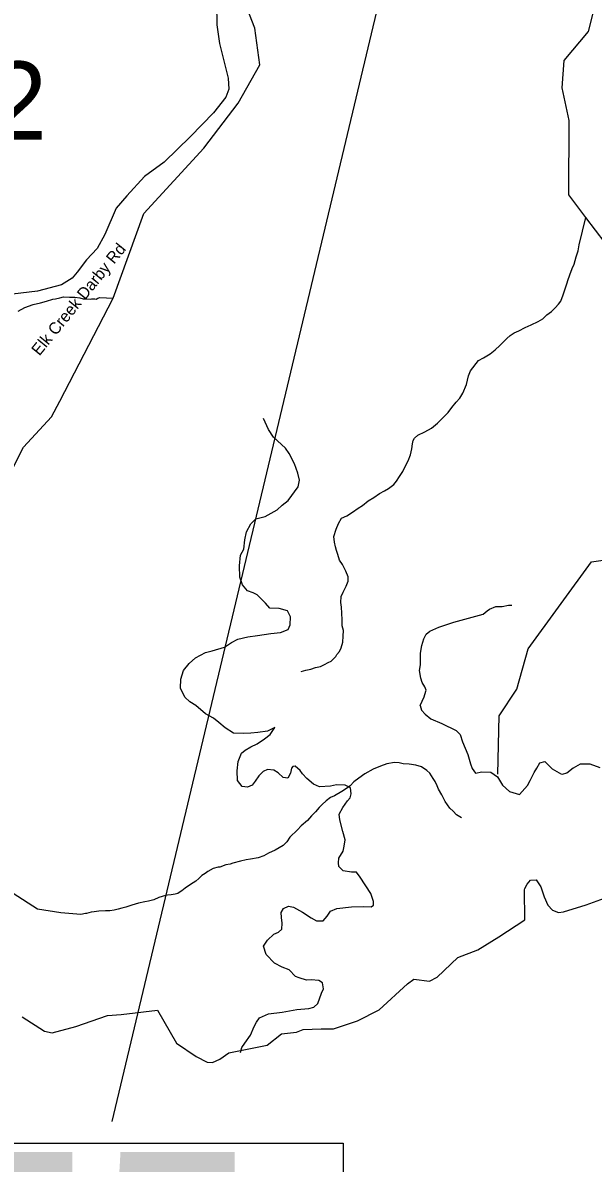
# Model space of a CAD drawing. Extents: x 1248224 to 1454986, y 825081 to 985870.
# Drawn here: x 1257767 to 1261423, y 862920 to 870230 of the extents above; entities that cross this region are included whole.
import ezdxf

# ---------------------------------------------------------------- set-up
doc = ezdxf.new("R2010")
doc.units = 0
for name, color, linetype in [('Exist Boundary Political CountyLine', 7, 'Continuous'), ('Exist Hydrographic Creek Single Shore', 7, 'Continuous'), ('Exist Hydrographic Misc Water Feature', 7, 'Continuous'), ('Exist Road Non-System Type 51', 7, 'Continuous'), ('Exist Road Secondary Structure Standard Bridge Number Label', 7, 'Continuous'), ('Exist Road Secondary Type 51 Attributed', 7, 'Continuous'), ('Exist Road Secondary Type 51 Label', 7, 'Continuous'), ('Exist Road Secondary Type 51 Number Label', 7, 'Continuous')]:
    doc.layers.add(name, color=color, linetype=linetype)

msp = doc.modelspace()

# ---------------------------------------------------------------- linework, layer by layer
at = {"layer": 'Exist Boundary Political CountyLine'}
for points in [[(1260985.6, 864480), (1260982.6, 864672), (1260983.6, 864680.2), (1260999.6, 864708.4), (1261021.6, 864734.8), (1261057.6, 864736.6), (1261087.6, 864691.6), (1261108.6, 864626.1), (1261131.6, 864572.8), (1261162.6, 864540.6), (1261199.6, 864527.6), (1261232.6, 864529.9), (1261377.6, 864575.3), (1261517.6, 864627.3)], [(1257763.5, 863857.1), (1257906.6, 863764.9), (1257954.3, 863755.3), (1258106.9, 863796.7), (1258308.9, 863866.7), (1258397.9, 863873), (1258629.6, 863900.8), (1258752.4, 863688.5), (1258878, 863602.6), (1258948, 863567.6), (1258983, 863564.4), (1259030.7, 863586.7), (1259087.9, 863628), (1259332.6, 863675.6), (1259424.9, 863748.9), (1259520.3, 863758.5), (1259564.8, 863777.6), (1259679.3, 863780.8), (1259758.8, 863780.8), (1259911.4, 863831.7), (1260051.3, 863901.7), (1260232.6, 864070.3), (1260272.3, 864098.9), (1260374.1, 864086.2), (1260421.8, 864111.7), (1260555.3, 864238.9), (1260682.5, 864286.7), (1260818.6, 864369.9), (1260985.6, 864480)]]:
    msp.add_lwpolyline(points, dxfattribs=at)
at = {"layer": 'Exist Hydrographic Creek Single Shore'}
for points in [[(1261646.5, 868709.1), (1261498.5, 868820.4), (1261375.5, 868982.3), (1261265.5, 869127.1), (1261269.5, 869603), (1261224.5, 869814), (1261237.4, 869987.8), (1261392.4, 870175), (1261475.5, 870508.2)], [(1258139.6, 864512.9), (1258010.5, 864524.3), (1257861.6, 864547), (1257705.6, 864648.6), (1257624.5, 864745.4), (1257452.6, 865198.6), (1257447.6, 865300.4), (1257198.5, 865705.9), (1257237.5, 865912), (1257176.5, 866113.4), (1257193.5, 866474.1), (1257403.5, 866850.7), (1257433.5, 867017.6), (1257691.5, 867353.8), (1257771.5, 867509.9), (1257951.5, 867703.1), (1258003.5, 867803.9), (1258346.9, 868463.9), (1258543.5, 869007.7), (1258926.5, 869427.1), (1259146.4, 869715.2), (1259287.1, 869960.8), (1259254.6, 870194.7), (1259150.8, 870460.3)], [(1257737.1, 868382), (1257779.7, 868405), (1257834.2, 868423.6), (1257880.5, 868434.4), (1257918.9, 868445.4), (1257959.3, 868458.4), (1257977.2, 868459.9), (1258003.5, 868467.2), (1258027.6, 868472.6), (1258065.6, 868471.6), (1258099.6, 868470.7), (1258131.5, 868465.9), (1258153.3, 868461.3), (1258177.3, 868460.7), (1258199.4, 868458.1), (1258207.4, 868460), (1258229.3, 868459.4), (1258237.3, 868459.2), (1258247.6, 868465), (1258261.6, 868468.6), (1258346.9, 868463.9)]]:
    msp.add_lwpolyline(points, dxfattribs=at)
at = {"layer": 'Exist Hydrographic Misc Water Feature'}
for points in [[(1259550.8, 866071.6), (1259581, 866080.8), (1259613.2, 866086.1), (1259643.6, 866097.2), (1259675.7, 866104.4), (1259700.1, 866115.8), (1259724.5, 866129.1), (1259742.7, 866138.8), (1259759, 866152.3), (1259773.5, 866167.9), (1259779.7, 866179.8), (1259796.3, 866199.4), (1259806.8, 866223.1), (1259817.8, 866258.8), (1259820.8, 866298.8), (1259821.8, 866334.8), (1259814.6, 866365), (1259813.5, 866403.1), (1259810.6, 866445.2), (1259809.5, 866483.3), (1259804.3, 866513.4), (1259807.3, 866551.3), (1259820, 866579), (1259839.1, 866618.6), (1259851.9, 866650.3), (1259852.6, 866678.3), (1259837.5, 866714.7), (1259816.6, 866757.2), (1259797.5, 866785.7), (1259786.3, 866822.1), (1259776.9, 866846.3), (1259771.5, 866870.5), (1259764.2, 866900.7), (1259761.3, 866936.8), (1259774.4, 866984.5), (1259789.4, 867020.1), (1259810.3, 867053.6), (1259844.6, 867068.8), (1259879.3, 867091.9), (1259916.1, 867118.9), (1259944.5, 867136.2), (1259981.3, 867165.4), (1260015.7, 867186.5), (1260052.5, 867211.5), (1260085, 867228.6), (1260111.4, 867244), (1260144, 867269.2), (1260162.6, 867290.8), (1260181.4, 867322.2), (1260202.2, 867353.7), (1260219.1, 867389.3), (1260236.1, 867422.9), (1260251, 867460.5), (1260260, 867498.4), (1260264.9, 867530.3), (1260269.4, 867552.2), (1260277.9, 867568), (1260298.3, 867585.4), (1260342.9, 867608.3), (1260385.5, 867631.2), (1260424.4, 867664.3), (1260465.5, 867703.2), (1260492.3, 867732.5), (1260517, 867763.9), (1260543.8, 867797.2), (1260568.7, 867824.6), (1260587.5, 867856.2), (1260610.9, 867911.5), (1260624.4, 867967.3), (1260635.3, 867999), (1260687, 868065.7), (1260719.4, 868082.9), (1260762.1, 868107.9), (1260794.7, 868133), (1260823.5, 868160.3), (1260850.3, 868187.5), (1260868.6, 868205.2), (1260891.3, 868224.6), (1260915.6, 868242), (1260946.1, 868255.1), (1260986.7, 868276.1), (1261025, 868293.1), (1261069.6, 868316), (1261100.1, 868333.2), (1261124.8, 868358.7), (1261155.4, 868379.9), (1261178, 868403.3), (1261200.6, 868426.7), (1261215.1, 868446.3), (1261230.2, 868486), (1261238.9, 868511.8), (1261256.1, 868563.4), (1261260.5, 868577.2), (1261273.5, 868615), (1261288.5, 868654.7), (1261301.2, 868682.3), (1261314.5, 868730), (1261325.5, 868767.7), (1261332.5, 868807.6), (1261375.5, 868982.3)], [(1260810.6, 865413.6), (1260820.6, 865787.6), (1260933.5, 865959.3), (1261006.5, 866217.2), (1261412.5, 866773.7), (1261605.5, 866802.7)], [(1260579.3, 865134.4), (1260545.8, 865153.3), (1260524.4, 865175.8), (1260502.8, 865196.5), (1260473.9, 865237.3), (1260453.1, 865281.8), (1260432, 865316.3), (1260422.5, 865338.7), (1260409.2, 865367), (1260397.7, 865385.3), (1260374.6, 865420), (1260356.9, 865436.4), (1260321.6, 865461.3), (1260285.8, 865470.2), (1260244, 865477.4), (1260204, 865480.3), (1260178.2, 865487), (1260150.2, 865487.7), (1260099.9, 865479), (1260059.4, 865464.1), (1260013, 865445.3), (1259958.1, 865414.6), (1259921.4, 865387.6), (1259888.8, 865364.4), (1259864.1, 865339.1), (1259841.7, 865321.6), (1259811.1, 865302.4), (1259764.4, 865275.5), (1259740, 865264.1), (1259711.5, 865242.9), (1259685, 865219.5), (1259666.4, 865200), (1259643.7, 865172.6), (1259616.9, 865145.3), (1259592.2, 865115.9), (1259551.3, 865083), (1259526.6, 865057.5), (1259479.3, 865008.7), (1259458.6, 864979.2), (1259435.9, 864955.8), (1259385.2, 864927.1), (1259342.5, 864906.2), (1259312.1, 864889), (1259275.8, 864877.9), (1259225.6, 864869.2), (1259197.5, 864863.9), (1259163.1, 864854.7), (1259112.8, 864842), (1259096.6, 864836.5), (1259068.5, 864831.3), (1259030, 864818.1), (1259018, 864816.5), (1258987.8, 864809.3), (1258953.4, 864790.1), (1258934.9, 864776.6), (1258914.6, 864763.1), (1258896, 864745.5), (1258875.7, 864728.1), (1258859.3, 864716.5), (1258834.9, 864701.1), (1258808.5, 864681.8), (1258786, 864666.3), (1258775.8, 864658.6), (1258759.6, 864649.1), (1258743.5, 864643.4), (1258717.3, 864640), (1258695.2, 864636.7), (1258681, 864635), (1258638.8, 864622.1), (1258606.3, 864606.9), (1258572.2, 864599.9), (1258548, 864594.4), (1258507.8, 864587.4), (1258465.4, 864574.6), (1258427.1, 864561.5), (1258400.8, 864554.2), (1258378.7, 864548.8), (1258352.4, 864541.4), (1258324.5, 864538.2), (1258296.4, 864536.9), (1258254.3, 864536), (1258224.1, 864530.8), (1258204.1, 864529.3), (1258175.8, 864520), (1258167.8, 864520.2), (1258139.6, 864512.9)]]:
    msp.add_lwpolyline(points, dxfattribs=at)
at = {"layer": 'Exist Road Non-System Type 51'}
for points in [[(1259381.5, 865711.8), (1259336.2, 865688.3), (1259272.5, 865679.9), (1259228.9, 865676.6), (1259183.6, 865674.9), (1259118.2, 865676.6), (1259064.6, 865710.1), (1259024.3, 865745.4), (1258989.1, 865772.2), (1258937.1, 865799.1), (1258876.7, 865854.5), (1258836.5, 865876.3), (1258804.6, 865906.5), (1258777.8, 865965.2), (1258779.5, 866022.3), (1258796.2, 866077.7), (1258833.1, 866123), (1258873.4, 866159.9), (1258938.8, 866193.5), (1258980.7, 866203.5), (1259059.5, 866228.1), (1259104.8, 866256.6), (1259145, 866278.4), (1259208.7, 866293.5), (1259270.8, 866301.9), (1259356.3, 866315.4), (1259418.4, 866322.1), (1259467, 866340.5), (1259480.4, 866370.7), (1259482.1, 866422.8), (1259463.6, 866461.4), (1259410, 866474.8), (1259349.6, 866478.1), (1259322.8, 866510), (1259268, 866562.4), (1259242.8, 866575.9), (1259207.6, 866589.3), (1259175.7, 866626.2), (1259157.3, 866676.5), (1259155.6, 866748.7), (1259162.3, 866817.5), (1259184.1, 866856.1), (1259190.8, 866914.9), (1259200.9, 866966.9), (1259227.7, 867018.9), (1259259.6, 867050.8), (1259319.9, 867065.9), (1259397.1, 867107.9), (1259429, 867138.1), (1259467.5, 867168.3), (1259531.2, 867255.5), (1259540.5, 867298.4), (1259530.5, 867343.7), (1259508.7, 867402.4), (1259473.5, 867467.9), (1259450, 867503.1), (1259374.5, 867573.6), (1259342.7, 867622.3), (1259309.1, 867692.7)], [(1260314.4, 865853), (1260339.3, 865909.4), (1260344.4, 865924.5), (1260351.1, 865951.4), (1260342.7, 865973.2), (1260325.9, 866001.7), (1260317.5, 866028.6), (1260309.2, 866077.3), (1260315.9, 866114.2), (1260315.9, 866157.8), (1260315.9, 866189.7), (1260324.2, 866238.4), (1260337.7, 866280.3), (1260351.1, 866310.5), (1260374.6, 866329), (1260433.3, 866355.8), (1260530.5, 866387.7), (1260622.8, 866412.9), (1260718.3, 866438.1), (1260743.5, 866459.9), (1260758.6, 866471.6), (1260798.8, 866488.4), (1260838.7, 866487.6), (1260880.6, 866496), (1260900.7, 866496)], [(1260314.4, 865853), (1260322.7, 865824.5), (1260346.2, 865797.6), (1260381.4, 865769.1), (1260451.9, 865737.2), (1260544.1, 865693.6), (1260570.9, 865668.4), (1260586, 865619.7), (1260619.6, 865539.2), (1260636.3, 865480.4), (1260647.4, 865449.2), (1260667.5, 865420.7), (1260709.4, 865427.4), (1260766.5, 865425.8), (1260808.4, 865395.5), (1260841.9, 865343.5), (1260885.5, 865303.2), (1260949.3, 865283.1), (1261001.2, 865340.2), (1261018, 865372), (1261044.8, 865424.1), (1261061.6, 865452.6), (1261081.7, 865486.2), (1261111.9, 865494.6)], [(1259161.8, 863628.7), (1259170.2, 863660.6), (1259190.3, 863689.1), (1259227.2, 863741.2), (1259250.7, 863794.9), (1259265.8, 863823.4), (1259284.2, 863851.9), (1259341.2, 863877.1), (1259428.4, 863888.8), (1259524, 863905.6), (1259599.5, 863912.3), (1259631.3, 863919.1), (1259658.2, 863944.2), (1259681.7, 864009.7), (1259693.4, 864038.2), (1259686.7, 864076.8), (1259663.2, 864090.2), (1259614.6, 864095.3), (1259586.1, 864093.6), (1259539.1, 864107), (1259514, 864117.1), (1259473.7, 864159), (1259428.4, 864175.8), (1259379.8, 864201), (1259326.1, 864256.4), (1259309.4, 864310.1), (1259334.5, 864348.7), (1259376.4, 864387.3), (1259404.9, 864400), (1259426.7, 864420.1), (1259428.4, 864458.7), (1259425, 864495.6), (1259423.4, 864527.5), (1259438.4, 864552.7), (1259470.3, 864567.8), (1259502.2, 864561.1), (1259559.2, 864529.2), (1259614.5, 864492.3), (1259649.7, 864473.8), (1259691.7, 864473.8), (1259716.8, 864504), (1259738.6, 864535.9), (1259780.6, 864552.7), (1259874.5, 864562.8), (1259951.6, 864566.1), (1259998.6, 864562.8), (1260015.3, 864574.5), (1260015.3, 864596.3), (1259996.9, 864648.3), (1259928.1, 864752.4), (1259906.3, 864786), (1259872.8, 864786), (1259820.8, 864792.7), (1259792.3, 864821.2), (1259790.6, 864844.7), (1259792.3, 864874.9), (1259820.5, 864919.1), (1259827.2, 864951), (1259832.2, 864992.9), (1259818.8, 865044.9), (1259798.7, 865120.5), (1259795.3, 865157.4), (1259817.1, 865199.3), (1259847.3, 865243), (1259865.7, 865261.4), (1259870.8, 865286.6), (1259867.4, 865325.2), (1259833.9, 865342), (1259778.5, 865345.3), (1259740, 865336.9), (1259669.5, 865331.9), (1259631, 865348.7), (1259587.4, 865385.6), (1259558.9, 865415.8), (1259545.4, 865437.6), (1259511.9, 865464.5), (1259496.8, 865462.8), (1259488.4, 865451.1), (1259483.4, 865419.2), (1259464.9, 865387.3), (1259436.4, 865392.3), (1259402.9, 865420.9), (1259376.1, 865439.3), (1259335.8, 865442.7), (1259307.3, 865430.9), (1259280.5, 865402.4), (1259257, 865368.8), (1259236.9, 865343.7), (1259206.7, 865330.2), (1259173.1, 865333.6), (1259143, 865372.2), (1259141.3, 865434.3), (1259148, 865494.7), (1259168.1, 865548.4), (1259192, 865567.5), (1259228.9, 865589.3), (1259269.2, 865607.8), (1259316.1, 865639.7), (1259351.3, 865668.2), (1259381.5, 865711.8)], [(1261467.7, 865453.6), (1261403.2, 865476.6), (1261338.7, 865476.6), (1261294.9, 865451.3), (1261253.5, 865419), (1261221.2, 865412.1), (1261161.3, 865444.4), (1261111.9, 865494.6)]]:
    msp.add_lwpolyline(points, dxfattribs=at)
at = {"layer": 'Exist Road Secondary Structure Standard Bridge Number Label'}
msp.add_line((1260257.9, 871245.8), (1258336.6, 863186.8), dxfattribs=at)
msp.add_lwpolyline([(1256105, 863047.8), (1259820.9, 863047.8), (1259820.9, 861511.3), (1256105, 861511.3)], close=True, dxfattribs=at)
at = {"layer": 'Exist Road Secondary Type 51 Attributed'}
for points in [[(1259008.5, 870350.4), (1259010.4, 870215.9), (1259027.4, 870096.5), (1259082.3, 869874.7), (1259088, 869804.6), (1259069.1, 869753.5), (1258988.2, 869652.7), (1258842.4, 869501), (1258673.9, 869336.2), (1258547, 869245.2), (1258433.4, 869120.1), (1258365.2, 869042.5), (1258291.7, 868873.2)], [(1258291.7, 868873.2), (1258244.4, 868782.3), (1258176.2, 868710.3), (1258115.6, 868630.7), (1258083.4, 868592.8), (1258015.2, 868551.1), (1257860.8, 868510.1), (1257701.8, 868489.3), (1257586.3, 868489.3), (1257525.7, 868491.2), (1257368.5, 868441.9), (1257292.8, 868430.6), (1257231.5, 868439.5), (1257115.9, 868509.7), (1257032.6, 868528.6), (1256975.8, 868534.3), (1256818.7, 868513.4), (1256689.9, 868507.8), (1256508.1, 868509.7), (1256438.1, 868492.6), (1256310.3, 868417.6), (1256096.9, 868282.5), (1256057.8, 868247.3), (1256032.3, 868215)]]:
    msp.add_lwpolyline(points, dxfattribs=at)

# ---------------------------------------------------------------- texts
at = {"layer": 'Exist Road Secondary Structure Standard Bridge Number Label'}
msp.add_text('355', height=1400, dxfattribs=at).set_placement((1256155.2, 861590.4))
at = {"layer": 'Exist Road Secondary Type 51 Label'}
msp.add_text('Elk Creek Darby Rd', height=75, rotation=50.86798, dxfattribs=at).set_placement((1257873.4, 868090.6))
at = {"layer": 'Exist Road Secondary Type 51 Number Label'}
msp.add_text('1162', height=500, dxfattribs=at).set_placement((1256435.1, 869481.6))

doc.saveas('drawing.dxf')
